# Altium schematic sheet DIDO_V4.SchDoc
size A2; SheetNumber: 2; SheetTotal: 2; SPICEModelCacheJMJTSHEM: <root> / <DocumentId>JMJTSHEM</DocumentId> / </root>
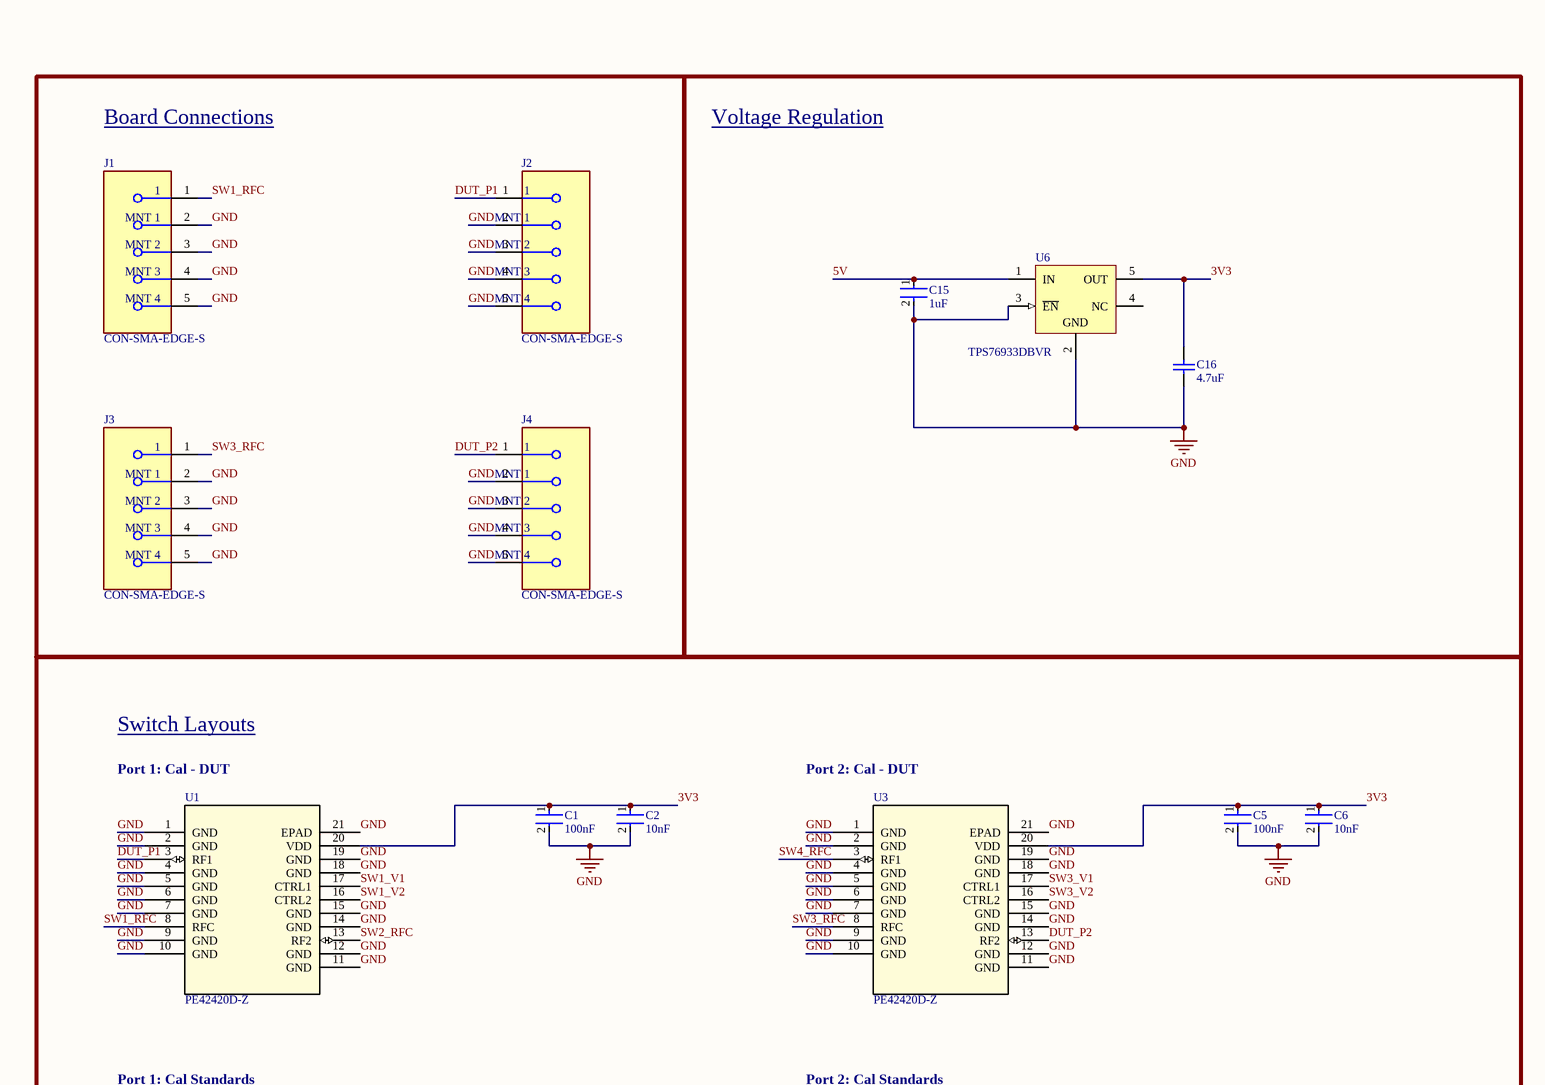
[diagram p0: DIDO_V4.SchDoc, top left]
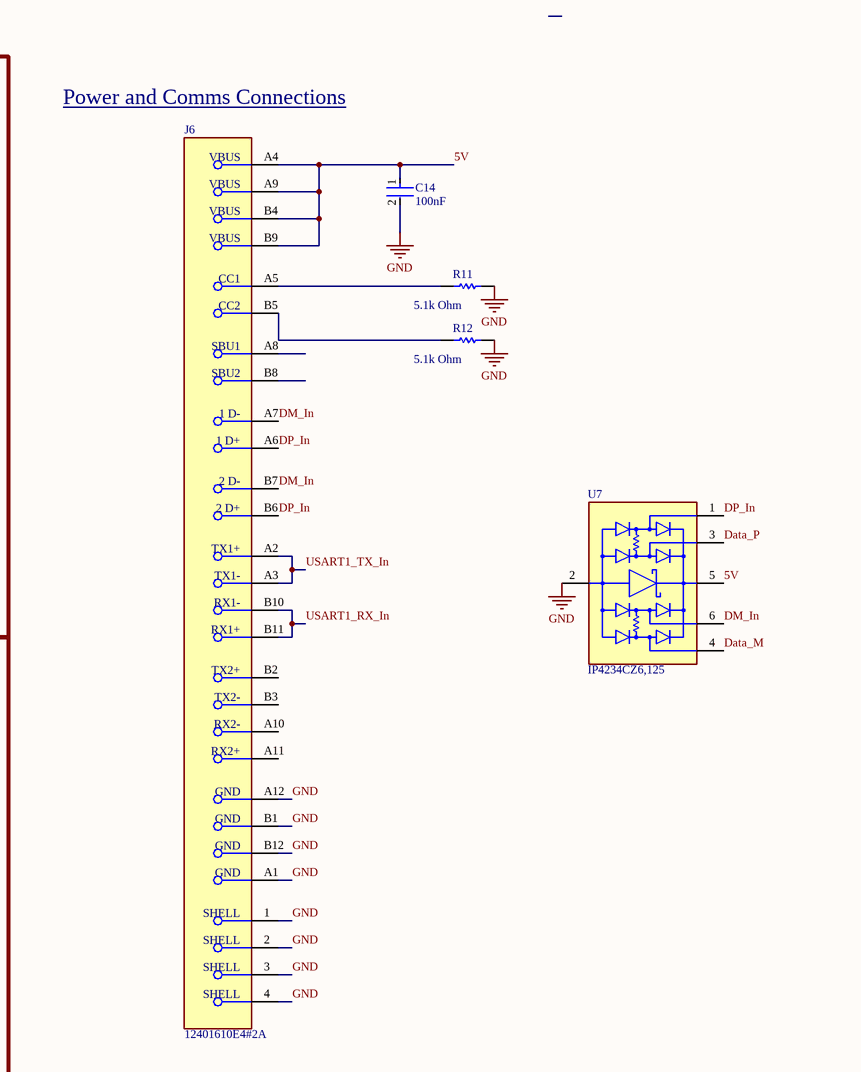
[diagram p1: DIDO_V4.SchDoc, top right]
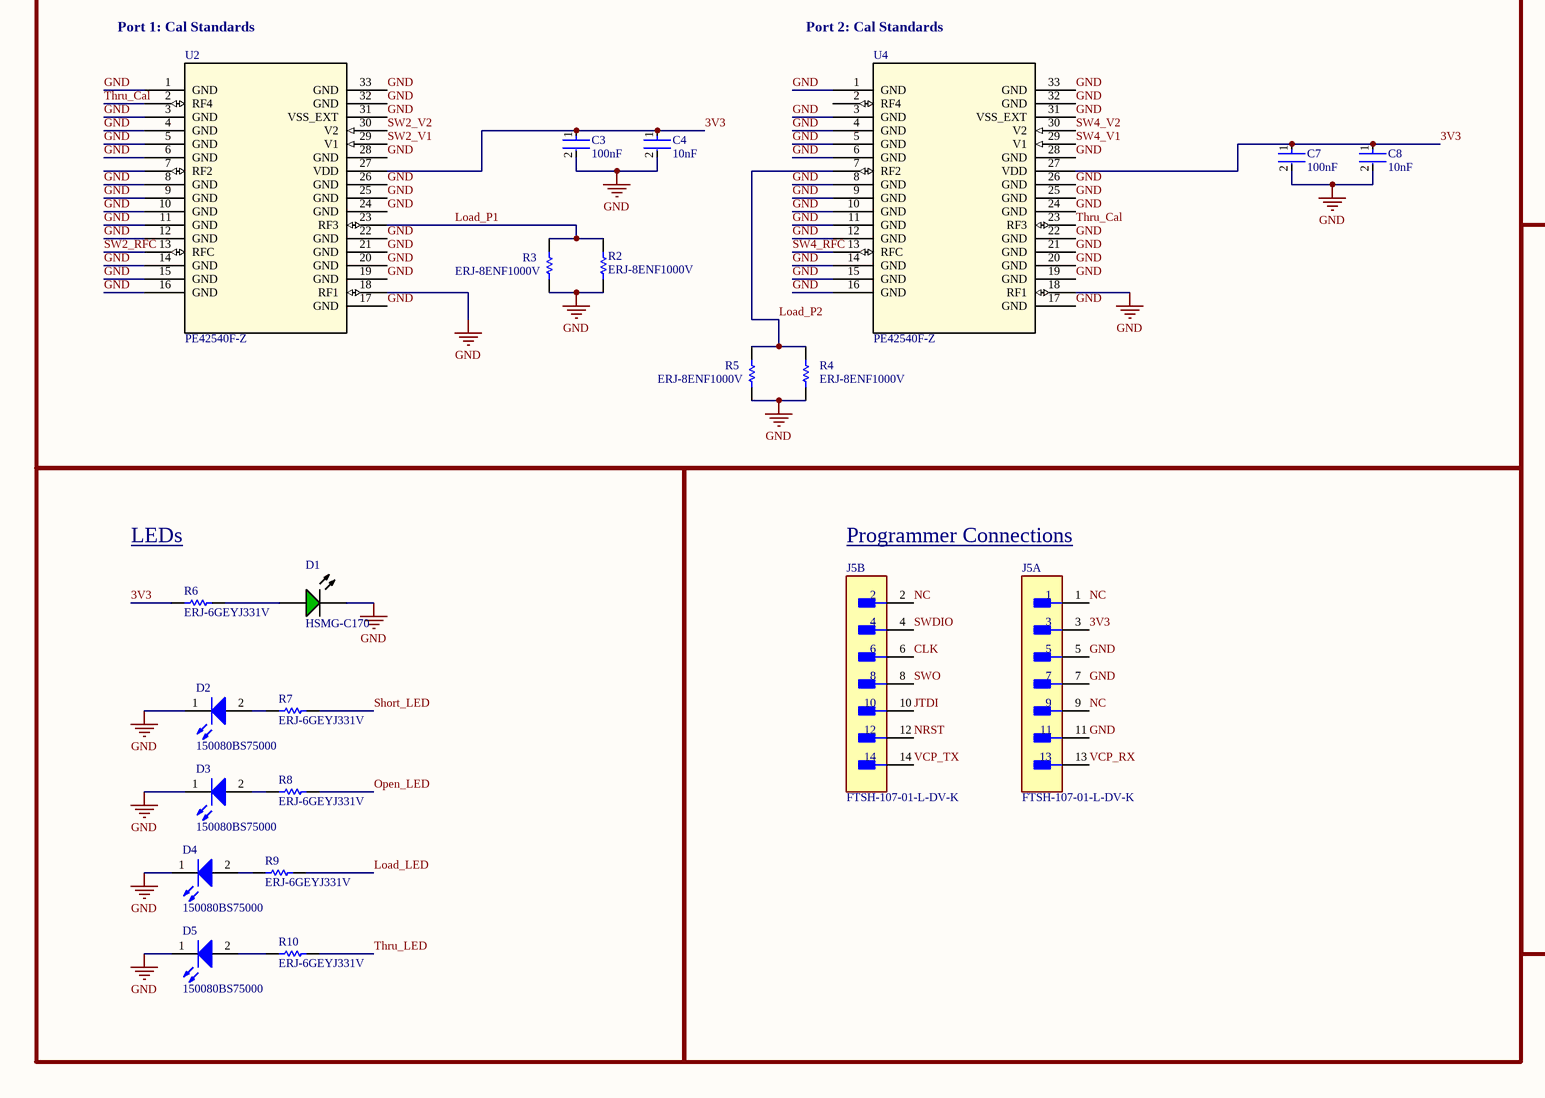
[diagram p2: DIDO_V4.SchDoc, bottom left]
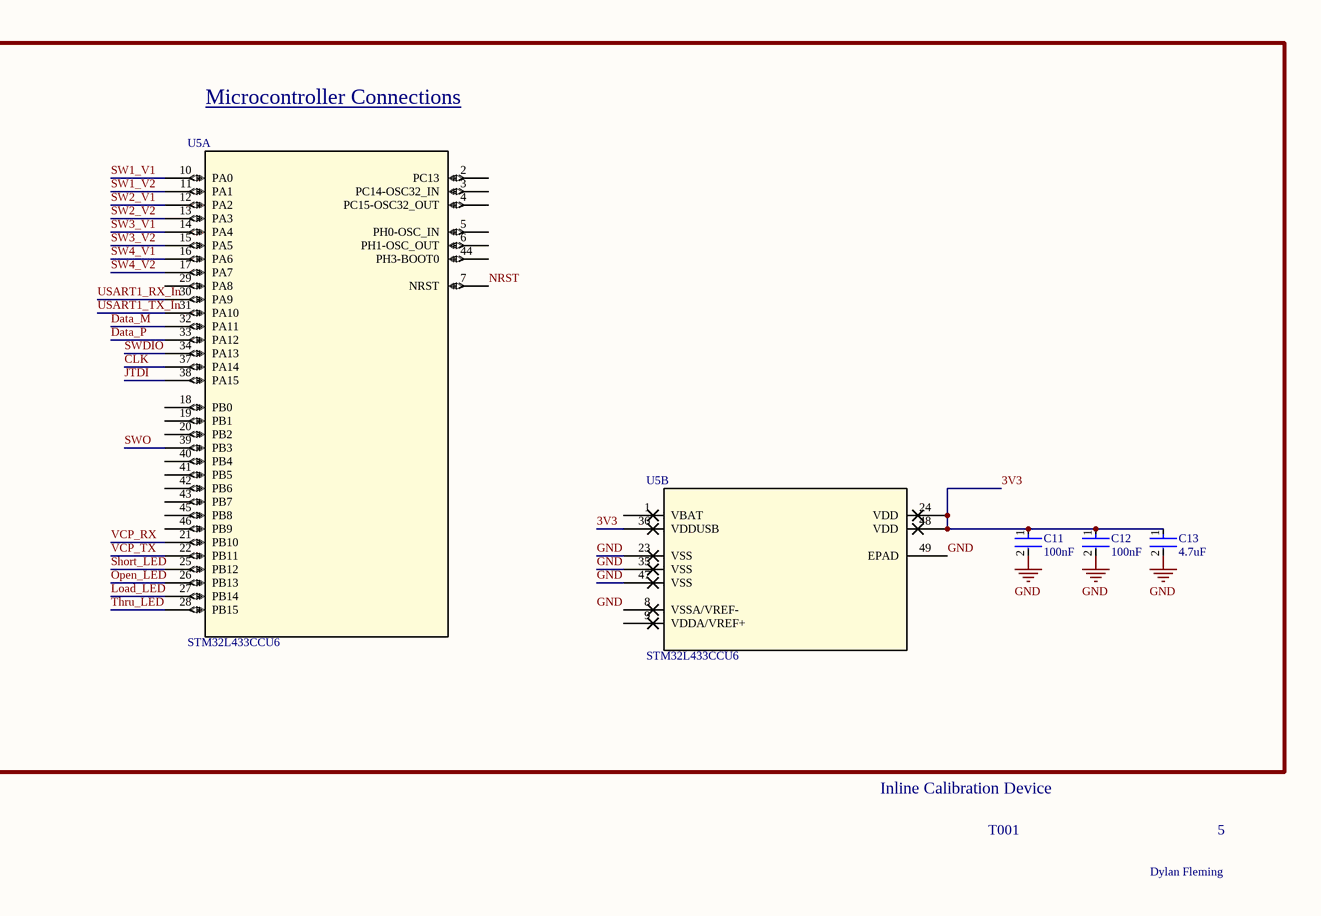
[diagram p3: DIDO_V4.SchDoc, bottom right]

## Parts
C1  100nF  [FP-1206-L_3_2_0_2-W_1_6_0-MFG]
C2  10nF  [FP-C0805C-DN-MFG]
C3  100nF  [FP-1206-L_3_2_0_2-W_1_6_0-MFG]
C4  10nF  [FP-C0805C-DN-MFG]
C5  100nF  [FP-1206-L_3_2_0_2-W_1_6_0-MFG]
C6  10nF  [FP-C0805C-DN-MFG]
C7  100nF  [FP-1206-L_3_2_0_2-W_1_6_0-MFG]
C8  10nF  [FP-C0805C-DN-MFG]
C11  100nF  [FP-1206-L_3_2_0_2-W_1_6_0-MFG]
C12  100nF  [FP-1206-L_3_2_0_2-W_1_6_0-MFG]
C13  4.7uF  [FP-C2012-125-0_2-IPC_C]
C14  100nF  [FP-1206-L_3_2_0_2-W_1_6_0-MFG]
C15  1uF  [FP-C1608-080-0_1-IPC_B]
C16  4.7uF  [CAPC2013X135X45LL10T25]
D1  HSMG-C170  [AVAG-HSMX-C170_V]
D2  150080BS75000  [WL-SMCW_0805_150080xx75000]
D3  150080BS75000  [WL-SMCW_0805_150080xx75000]
D4  150080BS75000  [WL-SMCW_0805_150080xx75000]
D5  150080BS75000  [WL-SMCW_0805_150080xx75000]
J1  CON-SMA-EDGE-S  [FP-CON-SMA-EDGE-S-MFG]
J2  CON-SMA-EDGE-S  [FP-CON-SMA-EDGE-S-MFG]
J3  CON-SMA-EDGE-S  [FP-CON-SMA-EDGE-S-MFG]
J4  CON-SMA-EDGE-S  [FP-CON-SMA-EDGE-S-MFG]
J5  FTSH-107-01-L-DV-K  [FP-FTSH-107-01-L-DV-K-MFG]  (parts A,B of 2)
J6  12401610E4#2A  [FP-12401610E4#2A-MFG]
R2  ERJ-8ENF1000V  [RESC3216X70X50NL05T20]
R3  ERJ-8ENF1000V  [RESC3216X70X50NL05T20]
R4  ERJ-8ENF1000V  [RESC3216X70X50NL05T20]
R5  ERJ-8ENF1000V  [RESC3216X70X50NL05T20]
R6  ERJ-6GEYJ331V  [RESC2013X70X40LL20T20]
R7  ERJ-6GEYJ331V  [RESC2013X70X40LL20T20]
R8  ERJ-6GEYJ331V  [RESC2013X70X40LL20T20]
R9  ERJ-6GEYJ331V  [RESC2013X70X40LL20T20]
R10  ERJ-6GEYJ331V  [RESC2013X70X40LL20T20]
R11  5.1k Ohm  [RESC3216X50X50NL20T25]
R12  5.1k Ohm  [RESC3216X50X50NL20T25]
U1  PE42420D-Z  [LGA20_4X4_PSM]
U2  PE42540F-Z  [PE42540G-Z]
U3  PE42420D-Z  [LGA20_4X4_PSM]
U4  PE42540F-Z  [PE42540G-Z]
U5  STM32L433CCU6  [UFQFPN48-7x7mm]  (parts A,B of 2)
U6  TPS76933DBVR  [DBV0005A_L]
U7  IP4234CZ6,125  [Nexperia_SOT457_MFG]

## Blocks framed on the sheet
Board Connections: J1-J4
Voltage Regulation: C15 C16 U6
Switch Layouts: C1-C8 R2-R5 U1-U4
Microcontroller Connections: C11-C13 U5
LEDs: D1-D5 R6-R10
Programmer Connections: J5

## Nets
GND: C1.2 C2.2 C3.2 C4.2 C5.2 C6.2 C7.2 C8.2 C11.2 C12.2 C13.2 C14.2 C15.2 C16.1 D1.2(K) D2.1(K) D3.1(K) D4.1(K) D5.1(K) J1.2(MNT_1) J1.3(MNT_2) J1.4(MNT_3) J1.5(MNT_4) J2.2(MNT_1) J2.3(MNT_2) J2.4(MNT_3) J2.5(MNT_4) J3.2(MNT_1) J3.3(MNT_2) J3.4(MNT_3) J3.5(MNT_4) J4.2(MNT_1) J4.3(MNT_2) J4.4(MNT_3) J4.5(MNT_4) J5.5 J5.7 J5.11 J6.1(SHELL) J6.2(SHELL) J6.3(SHELL) J6.4(SHELL) J6.A1(GND) J6.A12(GND) J6.B1(GND) J6.B12(GND) R2.2 R3.2 R4.2 R5.2 R11.2 R12.2 U1.1(GND) U1.2(GND) U1.4(GND) U1.5(GND) U1.6(GND) U1.7(GND) U1.9(GND) U1.10(GND) U1.11(GND) U1.12(GND) U1.14(GND) U1.15(GND) U1.18(GND) U1.19(GND) U1.21(EPAD) U2.1(GND) U2.3(GND) U2.4(GND) U2.5(GND) U2.6(GND) U2.8(GND) U2.9(GND) U2.10(GND) U2.11(GND) U2.12(GND) U2.14(GND) U2.15(GND) U2.16(GND) U2.17(GND) U2.18(RF1) U2.19(GND) U2.20(GND) U2.21(GND) U2.22(GND) U2.24(GND) U2.25(GND) U2.26(GND) U2.28(GND) U2.31(VSS_EXT) U2.32(GND) U2.33(GND) U3.1(GND) U3.2(GND) U3.4(GND) U3.5(GND) U3.6(GND) U3.7(GND) U3.9(GND) U3.10(GND) U3.11(GND) U3.12(GND) U3.14(GND) U3.15(GND) U3.18(GND) U3.19(GND) U3.21(EPAD) U4.1(GND) U4.3(GND) U4.4(GND) U4.5(GND) U4.6(GND) U4.8(GND) U4.9(GND) U4.10(GND) U4.11(GND) U4.12(GND) U4.14(GND) U4.15(GND) U4.16(GND) U4.17(GND) U4.18(RF1) U4.19(GND) U4.20(GND) U4.21(GND) U4.22(GND) U4.24(GND) U4.25(GND) U4.26(GND) U4.28(GND) U4.31(VSS_EXT) U4.32(GND) U4.33(GND) U5.23(VSS) U5.35(VSS) U5.47(VSS) U5.49(EPAD) U6.2(GND) U6.3(~{EN}) U7.2
3V3: C1.1 C2.1 C3.1 C4.1 C5.1 C6.1 C7.1 C8.1 C11.1 C12.1 C13.1 C16.2 J5.3 R6.1 U1.20(VDD) U2.27(VDD) U3.20(VDD) U4.27(VDD) U5.24(VDD) U5.36(VDDUSB) U5.48(VDD) U6.5(OUT)
5V: C14.1 C15.1 J6.A4(VBUS) J6.A9(VBUS) J6.B4(VBUS) J6.B9(VBUS) U6.1(IN) U7.5
CLK: J5.6 U5.37(PA14)
Data_M: U5.32(PA11) U7.4
Data_P: U5.33(PA12) U7.3
DM_In: J6.A7(1_D-) J6.B7(2_D-) U7.6
DP_In: J6.A6(1_D+) J6.B6(2_D+) U7.1
DUT_P1: J2.1 U1.3(RF1)
DUT_P2: J4.1 U3.13(RF2)
JTDI: J5.10 U5.38(PA15)
Load_LED: R9.1 U5.27(PB14)
Load_P1: R2.1 R3.1 U2.23(RF3)
Load_P2: R4.1 R5.1 U4.7(RF2)
NC: J5.1 J5.2 J5.9
NRST: J5.12 U5.7(NRST)
Open_LED: R8.1 U5.26(PB13)
Short_LED: R7.2 U5.25(PB12)
SW1_RFC: J1.1 U1.8(RFC)
SW1_V1: U1.17(CTRL1) U5.10(PA0)
SW1_V2: U1.16(CTRL2) U5.11(PA1)
SW2_RFC: U1.13(RF2) U2.13(RFC)
SW2_V1: U2.29(V1) U5.12(PA2)
SW2_V2: U2.30(V2) U5.13(PA3)
SW3_RFC: J3.1 U3.8(RFC)
SW3_V1: U3.17(CTRL1) U5.14(PA4)
SW3_V2: U3.16(CTRL2) U5.15(PA5)
SW4_RFC: U3.3(RF1) U4.13(RFC)
SW4_V1: U4.29(V1) U5.16(PA6)
SW4_V2: U4.30(V2) U5.17(PA7)
SWDIO: J5.4 U5.34(PA13)
SWO: J5.8 U5.39(PB3)
Thru_Cal: U2.2(RF4) U4.23(RF3)
Thru_LED: R10.1 U5.28(PB15)
USART1_RX_In: J6.B10(RX1-) J6.B11(RX1+) U5.30(PA9)
USART1_TX_In: J6.A2(TX1+) J6.A3(TX1-) U5.31(PA10)
VCP_RX: J5.13 U5.21(PB10)
VCP_TX: J5.14 U5.22(PB11)
NetD1_1: D1.1(A) R6.2
NetD2_2: D2.2(A) R7.1
NetD3_2: D3.2(A) R8.2
NetD4_2: D4.2(A) R9.2
NetD5_2: D5.2(A) R10.2
NetJ6_A5: J6.A5(CC1) R11.1
NetJ6_B5: J6.B5(CC2) R12.1

Not connected (* = marked no-connect by the designer): J6 A8(SBU1) A10(RX2-) A11(RX2+) B2(TX2+) B3(TX2-) B8(SBU2); U2 7(RF2); U4 2(RF4); U5 1(VBAT) 2(PC13) 3(PC14-OSC32_IN) 4(PC15-OSC32_OUT) 5(PH0-OSC_IN) 6(PH1-OSC_OUT) 8(VSSA/VREF-) 9(VDDA/VREF+) 18(PB0) 19(PB1) 20(PB2) 29(PA8) 40(PB4) 41(PB5) 42(PB6) 43(PB7) 44(PH3-BOOT0) 45(PB8) 46(PB9); U6 4(NC)

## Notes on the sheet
- Power and Comms Connections
- Port 1: Cal - DUT
- Port 2: Cal - DUT
- Port 1: Cal Standards
- Port 2: Cal Standards
- Inline Calibration Device
- T001
- Dylan Fleming
- 5
- Labels drawn without touching a wire or pin: GND

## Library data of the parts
C1 C3 C5 C7 C11 C12 C14 = CMP-04427-004798-1: General Purpose Ceramic Capacitor, 1206, 100nF, 10%, X7R, 15%, 100V
C2 C4 C6 C8 = CMP-2007-00259-2: CAP CER 10000PF 200V X7R 0805; Manufacturer Part Number: C0805C103K2RACTU; Manufacturer: KEMET; Material: Ceramic; Temperature Coefficient: 30ppm/°C; Capacitance: 10,000 pF; Tolerance: 0.1; Value: 10,000 pF
C13 = CMP-08246-000007-2: Multilayer Ceramic Capacitors 4.7μF ±10% 50V X5R SMD 0805
C15 = CMP-2000-06025-2: Multilayer Ceramic Capacitors 1μF ±10% 50V X5R SMD 0603
C16 = CMP-1662-00015-2: Chip Capacitor, 4.7 uF, +/- 10%, 16 V, -55 to 85 degC, 0805 (2012 Metric), RoHS, Tape and Reel; PartNumber: GRM21BR61C475KA88L; Voltage Rating (DC): 16 V; Type (Capacitors): X5R; Case\/Package: 0805
D1 = CMP-2000-05062-1: Chip LED, Green, 2.2 V, -40 to 85 degC, 2-Pin SMD, Pb-Free, Tape and Reel; Manufacturer: Avago; No. of Pins: 2; Peak Wavelength: 570nm; SVHC: NoSVHC(16-Jun-2014); Dominant Wavelength: 572nm; Forward Current If: 20mA; Viewing Angle: 170deg; Lens Shape: Rectangular; PIV Max: 5V; External Width: 1.25mm; LED Type: Standard; External Depth: 0.8mm; Opto Mounting Orientation: Top; Luminous Intensity: 15mcd; Luminous Intensity Min: 4mcd; Forward Voltage VF Max: 2.6V; External Length / Height: 2mm; Bulb Size: 1.25mmx1.4mm; Light Area Height: 1mm; Voltage Vf Typ: 2.2V
D2-D5 = CMP-1426-00008-6: NexarPartId: 29717779; Test Current: 20mA; Lens Style: Clear, Rectangular; Forward Current: 100mA; Power Dissipation: 105mW; Dominant Wavelength: 470nm; Reverse Voltage: 5V; Viewing Angle: 140°; Luminous Intensity: 145mcd; Color: Blue; Forward Voltage: 3.2V; Max Junction Temperature (Tj): 95°C; Peak Wavelength: 465nm
J1-J4 = CMP-204357-000001-1: CONN SMA JACK STR EDGE MNT; Manufacturer: RF Solutions Ltd.; Impedance: 50Ω; Conn Orientation: Right Angle; Is Female: yes; Number Of Contacts: 1; Frequency: 18GHz; Shielding: true
J5 = CMP-02766-001412-1: CONN HEADER SMD 14POS 1.27MM; Number of Contacts: 14; Gender: Male
J6 = CMP-15126-126516878-1: 12401610E4#2A Conn USB Type C RCP 24 POS 0.5mm Solder RA SMD 24 Terminal 1 Port Automotive; Gender: Receptacle; USB Standard: USB 3.1; Number of Contacts: 24; Current Rating: 5A
R2-R5 = CMP-2003-00016-1: Manufacturer: Panasonic
R6-R10 = CMP-1013-00062-2: Manufacturer: Panasonic
R11 R12 = CMP-2003-02609-1: Part Number: RG3216P-5101-B-T5; Manufacturer: Susumu
U1 U3 = PE42420D-Z: No Description Available; Mfr_Name: pSemi
U2 U4 = PE42540F-Z: No Description Available; Mfr_Name: Peregine Semiconductor
U5 = STM32L433CCU6: No Description Available; Mfr_Name: STMicroelectronics
U6 = CMP-0394-00574-2: Single Output LDO, 100 mA, Fixed 3.3 V Output, 2.7 to 10 V Input, with Low IQ, 5-pin SOT-23 (DBV), -40 to 125 degC, Green (RoHS & no Sb/Br); Manufacturer: Texas Instruments; Fixed Output Options(V): 3.3; Iq(Typ)(mA): 0.02; Rating: Catalog; Vin(Max)(V): 10; SubFamily: Single Channel LDO; Iout(Max)(A): 0.1; Vin(Min)(V): 2.7; Accuracy(%): 3; Vdo(Typ)(mV): 98
U7 = CMP-11424-78740506-1: IP4234CZ6,125 IP4234CZ6 Series 4 Channel Single USB 2.0 ESD Protection Surface Mount - TSOP-6; Manufacturer Lifecycle Status: RELEASED FOR SUPPLY; Leakage Current: 100nA; Min Breakdown Voltage: 6V; Power Line Protection: Yes; Peak Pulse Power: 100W; Number of Channels: 2; Number of Bidirectional Channels: 4; Polarity: Bidirectional; Operating Supply Voltage: 700mV; Reverse Standoff Voltage: 5.5V; Capacitance: 40pF; Direction: Unidirectional; Max Breakdown Voltage: 9V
